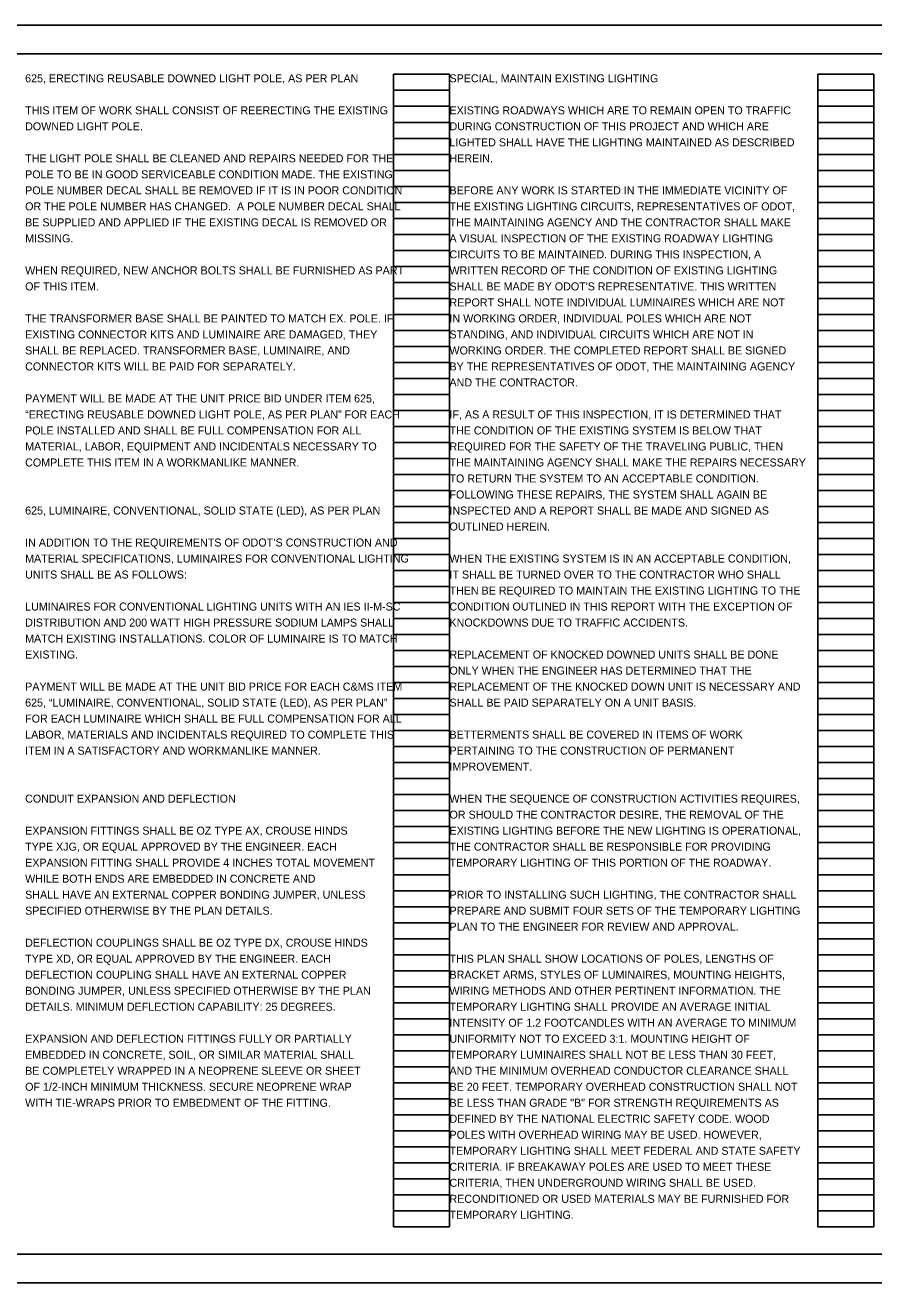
# Model space of a CAD drawing. Extents: x -7.6 to 41.7, y 0 to 22.5.
# Drawn here: x 2.4 to 17.24, y 0 to 22 of the extents above; entities that cross this region are included whole.
import ezdxf

# ---------------------------------------------------------------- set-up
doc = ezdxf.new("R2010")
doc.units = 0
for name, color, linetype in [('SH_Border', 7, 'Continuous'), ('SH_Cut_Line', 7, 'Continuous'), ('SH_Data', 7, 'Continuous'), ('SH_Text', 7, 'Continuous')]:
    doc.layers.add(name, color=color, linetype=linetype)

msp = doc.modelspace()

# ---------------------------------------------------------------- linework, layer by layer
at = {"layer": 'SH_Border'}
msp.add_lwpolyline([(1.5, 21.5), (33.5, 21.5), (33.5, 0.5), (1.5, 0.5)], close=True, dxfattribs=at)
at = {"layer": 'SH_Cut_Line'}
msp.add_lwpolyline([(0, 0), (34, 0), (34, 22), (0, 22)], close=True, dxfattribs=at)
at = {"layer": 'SH_Data'}
for p, q in [((8.84, 0.98), (8.84, 21.14)), ((8.84, 21.14), (9.82, 21.14)), ((9.82, 0.98), (9.82, 21.14)), ((16.26, 0.98), (16.26, 21.14)), ((16.26, 21.14), (17.24, 21.14)), ((17.24, 0.98), (17.24, 21.14)), ((8.84, 20.86), (9.82, 20.86)), ((16.26, 20.86), (17.24, 20.86)), ((8.84, 20.58), (9.82, 20.58)), ((16.26, 20.58), (17.24, 20.58)), ((8.84, 20.3), (9.82, 20.3)), ((16.26, 20.3), (17.24, 20.3)), ((8.84, 20.02), (9.82, 20.02)), ((16.26, 20.02), (17.24, 20.02)), ((8.84, 19.74), (9.82, 19.74)), ((16.26, 19.74), (17.24, 19.74)), ((8.84, 19.46), (9.82, 19.46)), ((16.26, 19.46), (17.24, 19.46)), ((8.84, 19.18), (9.82, 19.18)), ((16.26, 19.18), (17.24, 19.18)), ((8.84, 18.9), (9.82, 18.9)), ((16.26, 18.9), (17.24, 18.9)), ((8.84, 18.62), (9.82, 18.62)), ((16.26, 18.62), (17.24, 18.62)), ((8.84, 18.34), (9.82, 18.34)), ((16.26, 18.34), (17.24, 18.34)), ((8.84, 18.06), (9.82, 18.06)), ((16.26, 18.06), (17.24, 18.06)), ((8.84, 17.78), (9.82, 17.78)), ((16.26, 17.78), (17.24, 17.78)), ((8.84, 17.5), (9.82, 17.5)), ((16.26, 17.5), (17.24, 17.5)), ((8.84, 17.22), (9.82, 17.22)), ((16.26, 17.22), (17.24, 17.22)), ((8.84, 16.94), (9.82, 16.94)), ((16.26, 16.94), (17.24, 16.94)), ((8.84, 16.66), (9.82, 16.66)), ((16.26, 16.66), (17.24, 16.66)), ((8.84, 16.38), (9.82, 16.38)), ((16.26, 16.38), (17.24, 16.38)), ((8.84, 16.1), (9.82, 16.1)), ((16.26, 16.1), (17.24, 16.1)), ((8.84, 15.82), (9.82, 15.82)), ((16.26, 15.82), (17.24, 15.82)), ((8.84, 15.54), (9.82, 15.54)), ((16.26, 15.54), (17.24, 15.54)), ((8.84, 15.26), (9.82, 15.26)), ((16.26, 15.26), (17.24, 15.26)), ((8.84, 14.98), (9.82, 14.98)), ((16.26, 14.98), (17.24, 14.98)), ((8.84, 14.7), (9.82, 14.7)), ((16.26, 14.7), (17.24, 14.7)), ((8.84, 14.42), (9.82, 14.42)), ((16.26, 14.42), (17.24, 14.42)), ((8.84, 14.14), (9.82, 14.14)), ((16.26, 14.14), (17.24, 14.14)), ((8.84, 13.86), (9.82, 13.86)), ((16.26, 13.86), (17.24, 13.86)), ((8.84, 13.58), (9.82, 13.58)), ((16.26, 13.58), (17.24, 13.58)), ((8.84, 13.3), (9.82, 13.3)), ((16.26, 13.3), (17.24, 13.3)), ((8.84, 13.02), (9.82, 13.02)), ((16.26, 13.02), (17.24, 13.02)), ((8.84, 12.74), (9.82, 12.74)), ((16.26, 12.74), (17.24, 12.74)), ((8.84, 12.46), (9.82, 12.46)), ((16.26, 12.46), (17.24, 12.46)), ((8.84, 12.18), (9.82, 12.18)), ((16.26, 12.18), (17.24, 12.18)), ((8.84, 11.9), (9.82, 11.9)), ((16.26, 11.9), (17.24, 11.9)), ((8.84, 11.62), (9.82, 11.62)), ((16.26, 11.62), (17.24, 11.62)), ((8.84, 11.34), (9.82, 11.34)), ((16.26, 11.34), (17.24, 11.34)), ((8.84, 11.06), (9.82, 11.06)), ((16.26, 11.06), (17.24, 11.06)), ((8.84, 10.78), (9.82, 10.78)), ((16.26, 10.78), (17.24, 10.78)), ((8.84, 10.5), (9.82, 10.5)), ((16.26, 10.5), (17.24, 10.5)), ((8.84, 10.22), (9.82, 10.22)), ((16.26, 10.22), (17.24, 10.22)), ((8.84, 9.94), (9.82, 9.94)), ((16.26, 9.94), (17.24, 9.94)), ((8.84, 9.66), (9.82, 9.66)), ((16.26, 9.66), (17.24, 9.66)), ((8.84, 9.38), (9.82, 9.38)), ((16.26, 9.38), (17.24, 9.38)), ((8.84, 9.1), (9.82, 9.1)), ((16.26, 9.1), (17.24, 9.1)), ((8.84, 8.82), (9.82, 8.82)), ((16.26, 8.82), (17.24, 8.82)), ((8.84, 8.54), (9.82, 8.54)), ((16.26, 8.54), (17.24, 8.54)), ((8.84, 8.26), (9.82, 8.26)), ((16.26, 8.26), (17.24, 8.26)), ((8.84, 7.98), (9.82, 7.98)), ((16.26, 7.98), (17.24, 7.98)), ((8.84, 7.7), (9.82, 7.7)), ((16.26, 7.7), (17.24, 7.7)), ((8.84, 7.42), (9.82, 7.42)), ((16.26, 7.42), (17.24, 7.42)), ((8.84, 7.14), (9.82, 7.14)), ((16.26, 7.14), (17.24, 7.14)), ((8.84, 6.86), (9.82, 6.86)), ((16.26, 6.86), (17.24, 6.86)), ((8.84, 6.58), (9.82, 6.58)), ((16.26, 6.58), (17.24, 6.58)), ((8.84, 6.3), (9.82, 6.3)), ((16.26, 6.3), (17.24, 6.3)), ((8.84, 6.02), (9.82, 6.02)), ((16.26, 6.02), (17.24, 6.02)), ((8.84, 5.74), (9.82, 5.74)), ((16.26, 5.74), (17.24, 5.74)), ((8.84, 5.46), (9.82, 5.46)), ((16.26, 5.46), (17.24, 5.46)), ((8.84, 5.18), (9.82, 5.18)), ((16.26, 5.18), (17.24, 5.18)), ((8.84, 4.9), (9.82, 4.9)), ((16.26, 4.9), (17.24, 4.9)), ((8.84, 4.62), (9.82, 4.62)), ((16.26, 4.62), (17.24, 4.62)), ((8.84, 4.34), (9.82, 4.34)), ((16.26, 4.34), (17.24, 4.34)), ((8.84, 4.06), (9.82, 4.06)), ((16.26, 4.06), (17.24, 4.06)), ((8.84, 3.78), (9.82, 3.78)), ((16.26, 3.78), (17.24, 3.78)), ((8.84, 3.5), (9.82, 3.5)), ((16.26, 3.5), (17.24, 3.5)), ((8.84, 3.22), (9.82, 3.22)), ((16.26, 3.22), (17.24, 3.22)), ((8.84, 2.94), (9.82, 2.94)), ((16.26, 2.94), (17.24, 2.94)), ((8.84, 2.66), (9.82, 2.66)), ((16.26, 2.66), (17.24, 2.66)), ((8.84, 2.38), (9.82, 2.38)), ((16.26, 2.38), (17.24, 2.38)), ((8.84, 2.1), (9.82, 2.1)), ((16.26, 2.1), (17.24, 2.1)), ((8.84, 1.82), (9.82, 1.82)), ((16.26, 1.82), (17.24, 1.82)), ((8.84, 1.54), (9.82, 1.54)), ((16.26, 1.54), (17.24, 1.54)), ((8.84, 1.26), (9.82, 1.26)), ((16.26, 1.26), (17.24, 1.26)), ((8.84, 0.98), (9.82, 0.98)), ((16.26, 0.98), (17.24, 0.98))]:
    msp.add_line(p, q, dxfattribs=at)

# ---------------------------------------------------------------- texts
at = {"layer": 'SH_Text'}
for s, p in [('625, ERECTING REUSABLE DOWNED LIGHT POLE, AS PER PLAN', (2.4, 21)), ('SPECIAL, MAINTAIN EXISTING LIGHTING', (9.82, 21)), ('THIS ITEM OF WORK SHALL CONSIST OF REERECTING THE EXISTING ', (2.4, 20.44)), ('EXISTING ROADWAYS WHICH ARE TO REMAIN OPEN TO TRAFFIC', (9.82, 20.44)), ('DOWNED LIGHT POLE. ', (2.4, 20.16)), ('DURING CONSTRUCTION OF THIS PROJECT AND WHICH ARE', (9.82, 20.16)), ('LIGHTED SHALL HAVE THE LIGHTING MAINTAINED AS DESCRIBED', (9.82, 19.88)), ('THE LIGHT POLE SHALL BE CLEANED AND REPAIRS NEEDED FOR THE ', (2.4, 19.6)), ('HEREIN.', (9.82, 19.6)), ('POLE TO BE IN GOOD SERVICEABLE CONDITION MADE. THE EXISTING ', (2.4, 19.32)), ('POLE NUMBER DECAL SHALL BE REMOVED IF IT IS IN POOR CONDITION ', (2.4, 19.04)), ('BEFORE ANY WORK IS STARTED IN THE IMMEDIATE VICINITY OF', (9.82, 19.04)), ('OR THE POLE NUMBER HAS CHANGED.  A POLE NUMBER DECAL SHALL ', (2.4, 18.76)), ('THE EXISTING LIGHTING CIRCUITS, REPRESENTATIVES OF ODOT,', (9.82, 18.76)), ('BE SUPPLIED AND APPLIED IF THE EXISTING DECAL IS REMOVED OR ', (2.4, 18.48)), ('THE MAINTAINING AGENCY AND THE CONTRACTOR SHALL MAKE', (9.82, 18.48)), ('MISSING.', (2.4, 18.2)), ('A VISUAL INSPECTION OF THE EXISTING ROADWAY LIGHTING', (9.82, 18.2)), ('CIRCUITS TO BE MAINTAINED. DURING THIS INSPECTION, A', (9.82, 17.92)), ('WHEN REQUIRED, NEW ANCHOR BOLTS SHALL BE FURNISHED AS PART ', (2.4, 17.64)), ('WRITTEN RECORD OF THE CONDITION OF EXISTING LIGHTING', (9.82, 17.64)), ('OF THIS ITEM.', (2.4, 17.36)), ("SHALL BE MADE BY ODOT'S REPRESENTATIVE. THIS WRITTEN", (9.82, 17.36)), ('REPORT SHALL NOTE INDIVIDUAL LUMINAIRES WHICH ARE NOT', (9.82, 17.08)), ('THE TRANSFORMER BASE SHALL BE PAINTED TO MATCH EX. POLE. IF ', (2.4, 16.8)), ('IN WORKING ORDER, INDIVIDUAL POLES WHICH ARE NOT', (9.82, 16.8)), ('EXISTING CONNECTOR KITS AND LUMINAIRE ARE DAMAGED, THEY ', (2.4, 16.52)), ('STANDING, AND INDIVIDUAL CIRCUITS WHICH ARE NOT IN', (9.82, 16.52)), ('SHALL BE REPLACED. TRANSFORMER BASE, LUMINAIRE, AND ', (2.4, 16.24)), ('WORKING ORDER. THE COMPLETED REPORT SHALL BE SIGNED', (9.82, 16.24)), ('CONNECTOR KITS WILL BE PAID FOR SEPARATELY.', (2.4, 15.96)), ('BY THE REPRESENTATIVES OF ODOT, THE MAINTAINING AGENCY', (9.82, 15.96)), ('AND THE CONTRACTOR.', (9.82, 15.68)), ('PAYMENT WILL BE MADE AT THE UNIT PRICE BID UNDER ITEM 625, ', (2.4, 15.4)), ('“ERECTING REUSABLE DOWNED LIGHT POLE, AS PER PLAN” FOR EACH ', (2.4, 15.12)), ('IF, AS A RESULT OF THIS INSPECTION, IT IS DETERMINED THAT', (9.82, 15.12)), ('POLE INSTALLED AND SHALL BE FULL COMPENSATION FOR ALL ', (2.4, 14.84)), ('THE CONDITION OF THE EXISTING SYSTEM IS BELOW THAT', (9.82, 14.84)), ('MATERIAL, LABOR, EQUIPMENT AND INCIDENTALS NECESSARY TO ', (2.4, 14.56)), ('REQUIRED FOR THE SAFETY OF THE TRAVELING PUBLIC, THEN', (9.82, 14.56)), ('COMPLETE THIS ITEM IN A WORKMANLIKE MANNER.', (2.4, 14.28)), ('THE MAINTAINING AGENCY SHALL MAKE THE REPAIRS NECESSARY', (9.82, 14.28)), ('TO RETURN THE SYSTEM TO AN ACCEPTABLE CONDITION.', (9.82, 14)), ('FOLLOWING THESE REPAIRS, THE SYSTEM SHALL AGAIN BE', (9.82, 13.72)), ('625, LUMINAIRE, CONVENTIONAL, SOLID STATE (LED), AS PER PLAN', (2.4, 13.44)), ('INSPECTED AND A REPORT SHALL BE MADE AND SIGNED AS', (9.82, 13.44)), ('OUTLINED HEREIN.', (9.82, 13.16)), ('IN ADDITION TO THE REQUIREMENTS OF ODOT’S CONSTRUCTION AND ', (2.4, 12.88)), ('MATERIAL SPECIFICATIONS, LUMINAIRES FOR CONVENTIONAL LIGHTING ', (2.4, 12.6)), ('WHEN THE EXISTING SYSTEM IS IN AN ACCEPTABLE CONDITION,', (9.82, 12.6)), ('UNITS SHALL BE AS FOLLOWS: ', (2.4, 12.32)), ('IT SHALL BE TURNED OVER TO THE CONTRACTOR WHO SHALL', (9.82, 12.32)), ('THEN BE REQUIRED TO MAINTAIN THE EXISTING LIGHTING TO THE', (9.82, 12.04)), ('LUMINAIRES FOR CONVENTIONAL LIGHTING UNITS WITH AN IES II-M-SC ', (2.4, 11.76)), ('CONDITION OUTLINED IN THIS REPORT WITH THE EXCEPTION OF', (9.82, 11.76)), ('DISTRIBUTION AND 200 WATT HIGH PRESSURE SODIUM LAMPS SHALL ', (2.4, 11.48)), ('KNOCKDOWNS DUE TO TRAFFIC ACCIDENTS.', (9.82, 11.48)), ('MATCH EXISTING INSTALLATIONS. COLOR OF LUMINAIRE IS TO MATCH ', (2.4, 11.2)), ('EXISTING.', (2.4, 10.92)), ('REPLACEMENT OF KNOCKED DOWNED UNITS SHALL BE DONE', (9.82, 10.92)), ('ONLY WHEN THE ENGINEER HAS DETERMINED THAT THE', (9.82, 10.64)), ('PAYMENT WILL BE MADE AT THE UNIT BID PRICE FOR EACH C&MS ITEM ', (2.4, 10.36)), ('REPLACEMENT OF THE KNOCKED DOWN UNIT IS NECESSARY AND', (9.82, 10.36)), ('625, “LUMINAIRE, CONVENTIONAL, SOLID STATE (LED), AS PER PLAN” ', (2.4, 10.08)), ('SHALL BE PAID SEPARATELY ON A UNIT BASIS.', (9.82, 10.08)), ('FOR EACH LUMINAIRE WHICH SHALL BE FULL COMPENSATION FOR ALL ', (2.4, 9.8)), ('LABOR, MATERIALS AND INCIDENTALS REQUIRED TO COMPLETE THIS ', (2.4, 9.52)), ('BETTERMENTS SHALL BE COVERED IN ITEMS OF WORK', (9.82, 9.52)), ('ITEM IN A SATISFACTORY AND WORKMANLIKE MANNER.', (2.4, 9.24)), ('PERTAINING TO THE CONSTRUCTION OF PERMANENT', (9.82, 9.24)), ('IMPROVEMENT.', (9.82, 8.96)), ('CONDUIT EXPANSION AND DEFLECTION', (2.4, 8.4)), ('WHEN THE SEQUENCE OF CONSTRUCTION ACTIVITIES REQUIRES,', (9.82, 8.4)), ('OR SHOULD THE CONTRACTOR DESIRE, THE REMOVAL OF THE', (9.82, 8.12)), ('EXPANSION FITTINGS SHALL BE OZ TYPE AX, CROUSE HINDS', (2.4, 7.84)), ('EXISTING LIGHTING BEFORE THE NEW LIGHTING IS OPERATIONAL,', (9.82, 7.84)), ('TYPE XJG, OR EQUAL APPROVED BY THE ENGINEER. EACH', (2.4, 7.56)), ('THE CONTRACTOR SHALL BE RESPONSIBLE FOR PROVIDING', (9.82, 7.56)), ('EXPANSION FITTING SHALL PROVIDE 4 INCHES TOTAL MOVEMENT', (2.4, 7.28)), ('TEMPORARY LIGHTING OF THIS PORTION OF THE ROADWAY.', (9.82, 7.28)), ('WHILE BOTH ENDS ARE EMBEDDED IN CONCRETE AND', (2.4, 7)), ('SHALL HAVE AN EXTERNAL COPPER BONDING JUMPER, UNLESS', (2.4, 6.72)), ('PRIOR TO INSTALLING SUCH LIGHTING, THE CONTRACTOR SHALL', (9.82, 6.72)), ('SPECIFIED OTHERWISE BY THE PLAN DETAILS.', (2.4, 6.44)), ('PREPARE AND SUBMIT FOUR SETS OF THE TEMPORARY LIGHTING', (9.82, 6.44)), ('PLAN TO THE ENGINEER FOR REVIEW AND APPROVAL.', (9.82, 6.16)), ('DEFLECTION COUPLINGS SHALL BE OZ TYPE DX, CROUSE HINDS', (2.4, 5.88)), ('TYPE XD, OR EQUAL APPROVED BY THE ENGINEER. EACH', (2.4, 5.6)), ('THIS PLAN SHALL SHOW LOCATIONS OF POLES, LENGTHS OF', (9.82, 5.6)), ('DEFLECTION COUPLING SHALL HAVE AN EXTERNAL COPPER', (2.4, 5.32)), ('BRACKET ARMS, STYLES OF LUMINAIRES, MOUNTING HEIGHTS,', (9.82, 5.32)), ('BONDING JUMPER, UNLESS SPECIFIED OTHERWISE BY THE PLAN', (2.4, 5.04)), ('WIRING METHODS AND OTHER PERTINENT INFORMATION. THE', (9.82, 5.04)), ('DETAILS. MINIMUM DEFLECTION CAPABILITY: 25 DEGREES.', (2.4, 4.76)), ('TEMPORARY LIGHTING SHALL PROVIDE AN AVERAGE INITIAL', (9.82, 4.76)), ('INTENSITY OF 1.2 FOOTCANDLES WITH AN AVERAGE TO MINIMUM', (9.82, 4.48)), ('EXPANSION AND DEFLECTION FITTINGS FULLY OR PARTIALLY', (2.4, 4.2)), ('UNIFORMITY NOT TO EXCEED 3:1. MOUNTING HEIGHT OF', (9.82, 4.2)), ('EMBEDDED IN CONCRETE, SOIL, OR SIMILAR MATERIAL SHALL', (2.4, 3.92)), ('TEMPORARY LUMINAIRES SHALL NOT BE LESS THAN 30 FEET,', (9.82, 3.92)), ('BE COMPLETELY WRAPPED IN A NEOPRENE SLEEVE OR SHEET', (2.4, 3.64)), ('AND THE MINIMUM OVERHEAD CONDUCTOR CLEARANCE SHALL', (9.82, 3.64)), ('OF 1/2-INCH MINIMUM THICKNESS. SECURE NEOPRENE WRAP', (2.4, 3.36)), ('BE 20 FEET. TEMPORARY OVERHEAD CONSTRUCTION SHALL NOT', (9.82, 3.36)), ('WITH TIE-WRAPS PRIOR TO EMBEDMENT OF THE FITTING.', (2.4, 3.08)), ('BE LESS THAN GRADE "B" FOR STRENGTH REQUIREMENTS AS', (9.82, 3.08)), ('DEFINED BY THE NATIONAL ELECTRIC SAFETY CODE. WOOD', (9.82, 2.8)), ('POLES WITH OVERHEAD WIRING MAY BE USED. HOWEVER,', (9.82, 2.52)), ('TEMPORARY LIGHTING SHALL MEET FEDERAL AND STATE SAFETY', (9.82, 2.24)), ('CRITERIA. IF BREAKAWAY POLES ARE USED TO MEET THESE', (9.82, 1.96)), ('CRITERIA, THEN UNDERGROUND WIRING SHALL BE USED.', (9.82, 1.68)), ('RECONDITIONED OR USED MATERIALS MAY BE FURNISHED FOR', (9.82, 1.4)), ('TEMPORARY LIGHTING.', (9.82, 1.12))]:
    msp.add_text(s, height=0.14, dxfattribs=at).set_placement(p)

doc.saveas('drawing.dxf')
